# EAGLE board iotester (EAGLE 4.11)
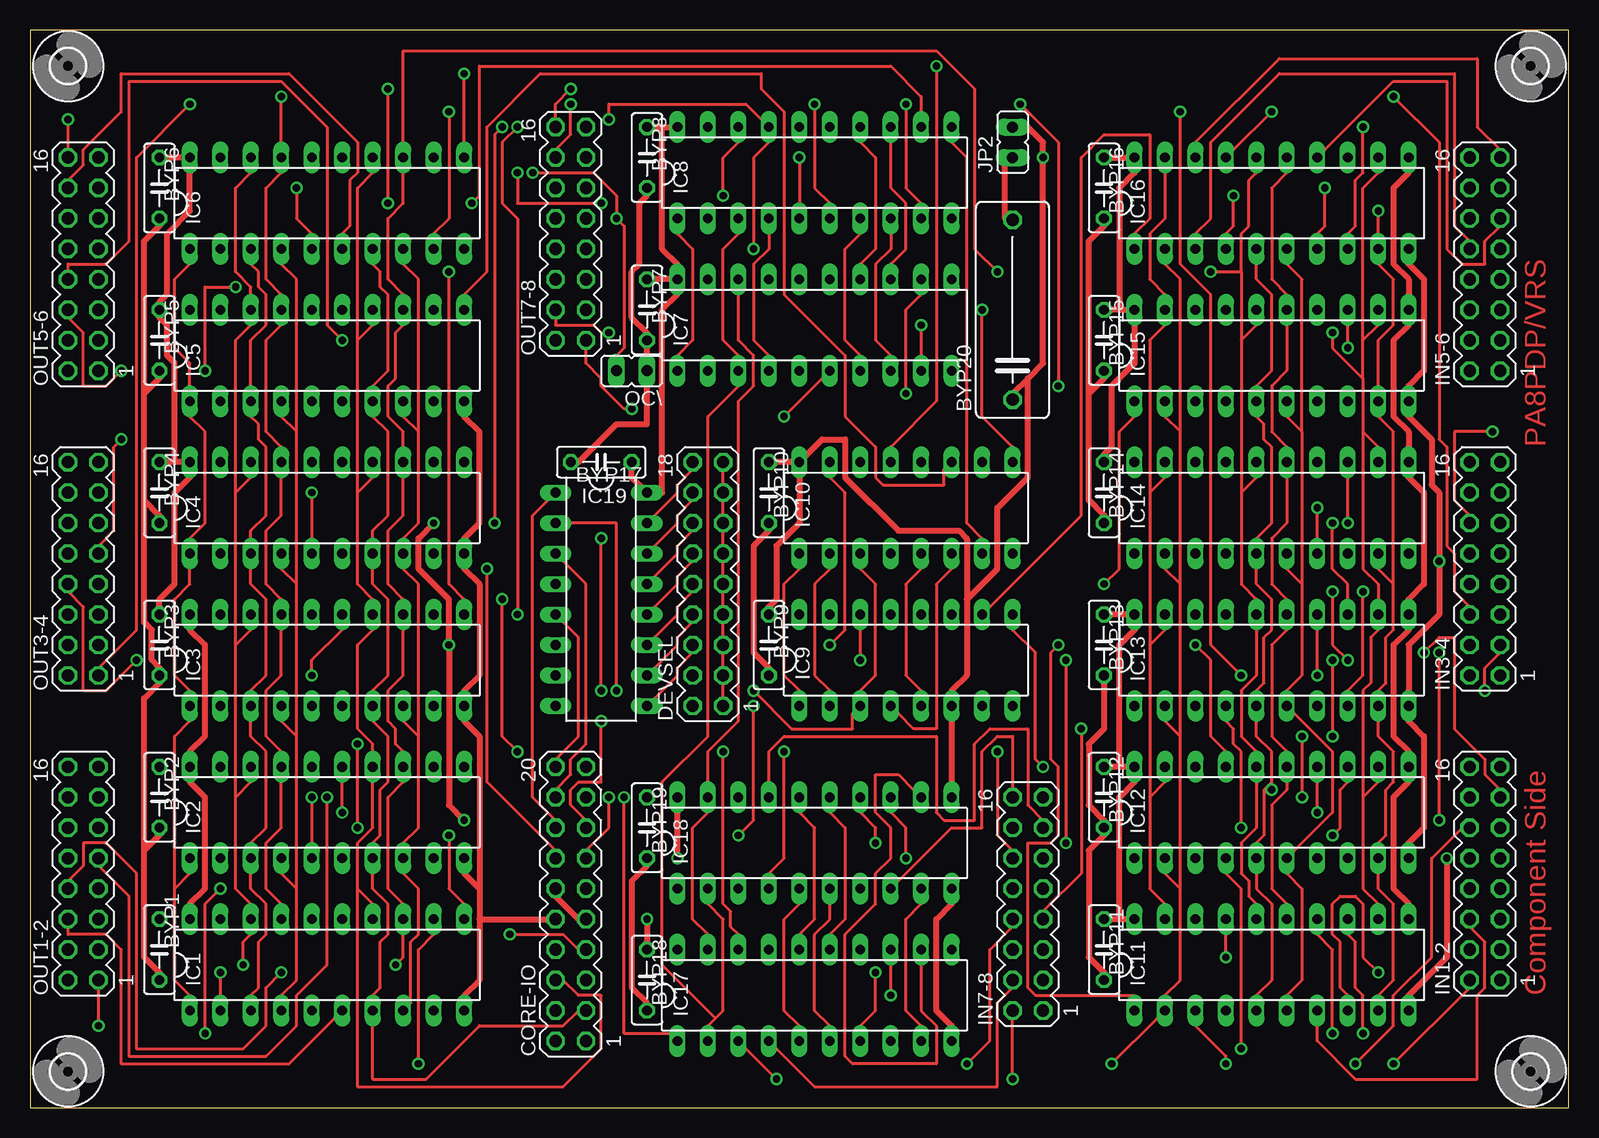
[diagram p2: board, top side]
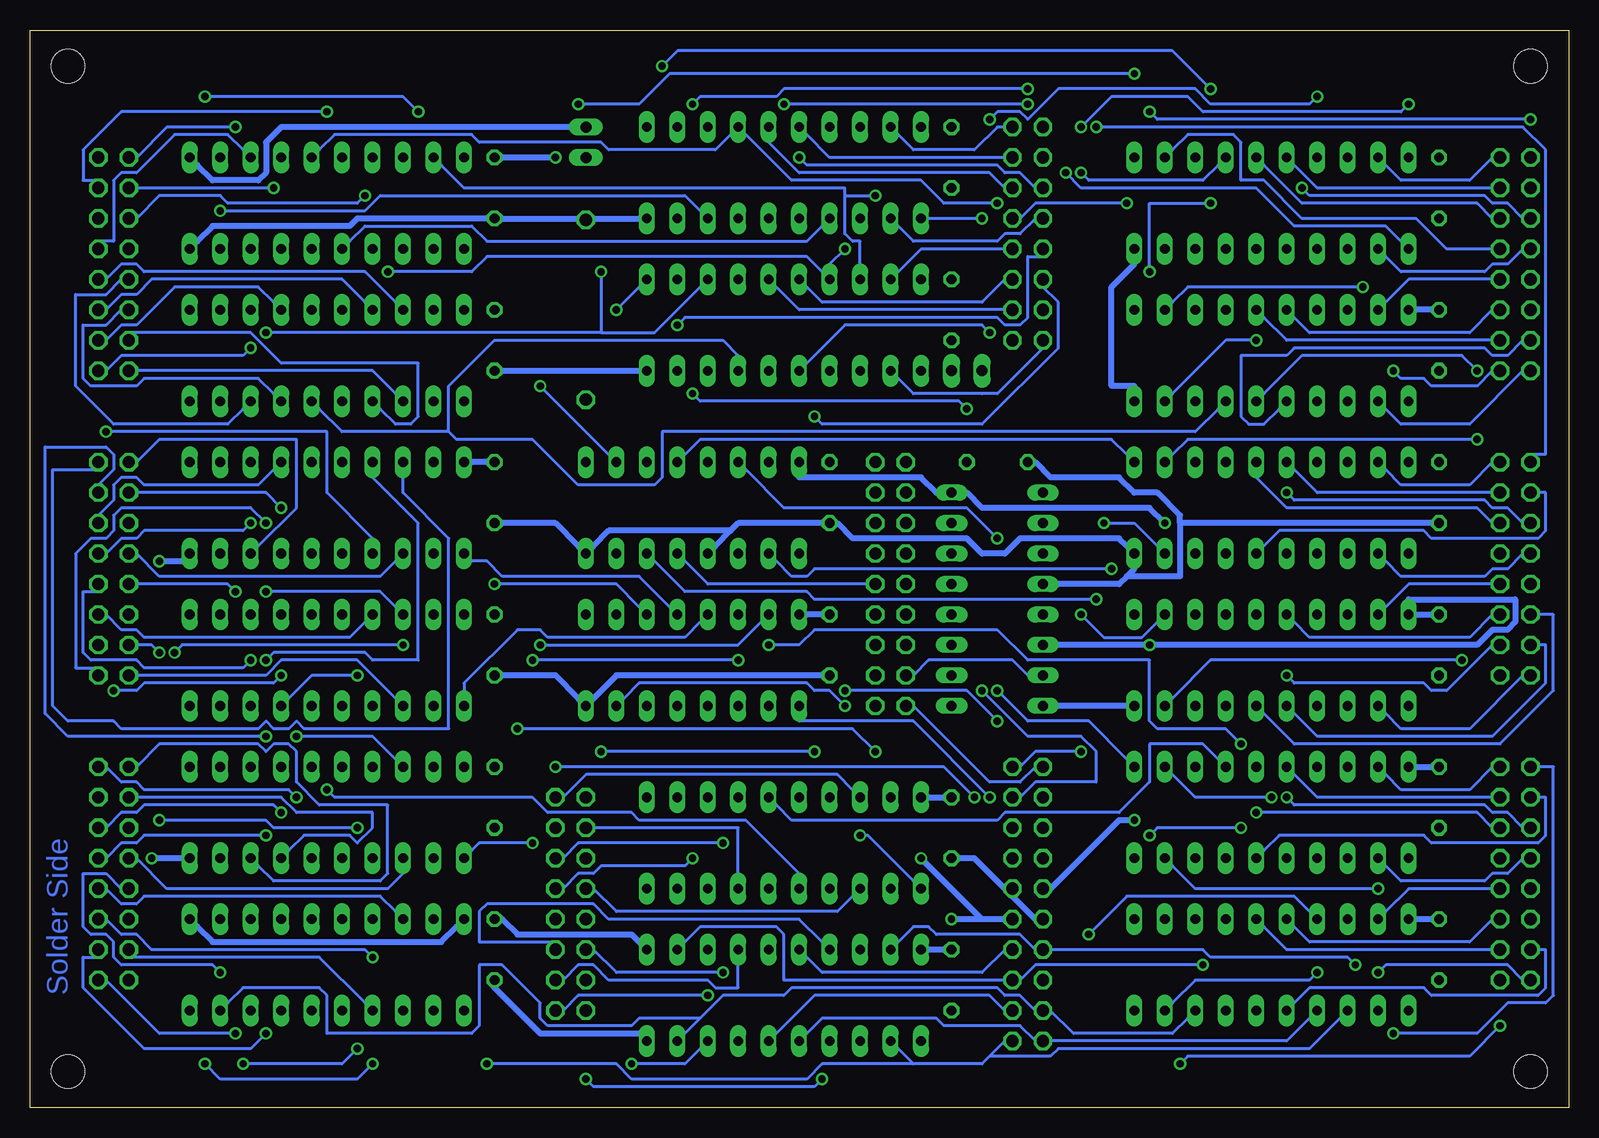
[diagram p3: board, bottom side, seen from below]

Size 128.25 x 89.84 mm. Coordinates in mm from the lower left corner, seen from the top.
Outline: 0,0 128.25,0 128.25,89.84 0,89.84 0,0
Copper layers (1*16): Top 0.035mm / dielectric 1.5mm / Bottom 0.035mm
Design rules "olimex10mil": minimum track width 10mil, minimum drill 24mil, track to track 10mil, track to pad 10mil, pad to pad 10mil, via to via 10mil, smd to smd 10mil, copper to edge 40mil, drill to drill 10mil, minimum pad ring 10mil, minimum via ring 8mil, stop-mask expansion 0mil, vias tented up to drill 0mil, thermal gap 10mil
Net classes: 1 Power: width 0.508 mm, drill 0.254 mm, clearance 0.254 mm

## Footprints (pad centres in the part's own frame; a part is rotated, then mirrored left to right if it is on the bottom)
C050-025X075 = drill 0.813 octagon: 1 -2.54,0; 2 2.54,0
C150-064X183 = drill 1.016 octagon: 1 -7.493,0; 2 7.493,0
MA10-2 = drill 1.016 octagon: 1 -11.43,-1.27; 2 -11.43,1.27; 3 -8.89,-1.27; 4 -8.89,1.27; 5 -6.35,-1.27; 6 -6.35,1.27; 7 -3.81,-1.27; 8 -3.81,1.27; 9 -1.27,-1.27; 10 -1.27,1.27; 11 1.27,-1.27; 12 1.27,1.27; 13 3.81,-1.27; 14 3.81,1.27; 15 6.35,-1.27; 16 6.35,1.27; 17 8.89,-1.27; 18 8.89,1.27; 19 11.43,-1.27; 20 11.43,1.27
MA09-2 = drill 1.016 octagon: 1 -10.16,-1.27; 2 -10.16,1.27; 3 -7.62,-1.27; 4 -7.62,1.27; 5 -5.08,-1.27; 6 -5.08,1.27; 7 -2.54,-1.27; 8 -2.54,1.27; 9 0,-1.27; 10 0,1.27; 11 2.54,-1.27; 12 2.54,1.27; 13 5.08,-1.27; 14 5.08,1.27; 15 7.62,-1.27; 16 7.62,1.27; 17 10.16,-1.27; 18 10.16,1.27
DIL20 = drill 0.813 long: 1 -11.43,-3.81; 2 -8.89,-3.81; 3 -6.35,-3.81; 4 -3.81,-3.81; 5 -1.27,-3.81; 6 1.27,-3.81; 7 3.81,-3.81; 8 6.35,-3.81; 9 8.89,-3.81; 10 11.43,-3.81; 11 11.43,3.81; 12 8.89,3.81; 13 6.35,3.81; 14 3.81,3.81; 15 1.27,3.81; 16 -1.27,3.81; 17 -3.81,3.81; 18 -6.35,3.81; 19 -8.89,3.81; 20 -11.43,3.81
DIL16 = drill 0.813 long: 1 -8.89,-3.81; 2 -6.35,-3.81; 3 -3.81,-3.81; 4 -1.27,-3.81; 5 1.27,-3.81; 6 3.81,-3.81; 7 6.35,-3.81; 8 8.89,-3.81; 9 8.89,3.81; 10 6.35,3.81; 11 3.81,3.81; 12 1.27,3.81; 13 -1.27,3.81; 14 -3.81,3.81; 15 -6.35,3.81; 16 -8.89,3.81
MA08-2 = drill 1.016 octagon: 1 -8.89,-1.27; 2 -8.89,1.27; 3 -6.35,-1.27; 4 -6.35,1.27; 5 -3.81,-1.27; 6 -3.81,1.27; 7 -1.27,-1.27; 8 -1.27,1.27; 9 1.27,-1.27; 10 1.27,1.27; 11 3.81,-1.27; 12 3.81,1.27; 13 6.35,-1.27; 14 6.35,1.27; 15 8.89,-1.27; 16 8.89,1.27
JP1 = drill 0.914 long: 1 0,-1.27; 2 0,1.27
2,8 = hole 2.8: 0,0

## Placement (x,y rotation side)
BYP1  0.1uf  [C050-025X075]  10.79,13.17 270 top
BYP2  0.1uf  [C050-025X075]  10.79,25.87 270 top
BYP3  0.1uf  [C050-025X075]  10.79,38.57 270 top
BYP4  0.1uf  [C050-025X075]  10.79,51.27 270 top
BYP5  0.1uf  [C050-025X075]  10.79,63.97 270 top
BYP6  0.1uf  [C050-025X075]  10.79,76.67 270 top
BYP7  0.1uf  [C050-025X075]  51.43,66.51 270 top
BYP8  0.1uf  [C050-025X075]  51.43,79.21 270 top
BYP9  0.1uf  [C050-025X075]  61.59,38.57 270 top
BYP10  0.1uf  [C050-025X075]  61.59,51.27 270 top
BYP11  0.1uf  [C050-025X075]  89.53,13.17 270 top
BYP12  0.1uf  [C050-025X075]  89.53,25.87 270 top
BYP13  0.1uf  [C050-025X075]  89.53,38.57 270 top
BYP14  0.1uf  [C050-025X075]  89.53,51.27 270 top
BYP15  0.1uf  [C050-025X075]  89.53,63.97 270 top
BYP16  0.1uf  [C050-025X075]  89.53,76.67 270 top
BYP17  0.1uf  [C050-025X075]  47.62,53.81 180 top
BYP18  0.1uf  [C050-025X075]  51.43,10.63 270 top
BYP19  0.1uf  [C050-025X075]  51.43,23.33 270 top
BYP20  100uf 25V  [C150-064X183]  81.91,66.51 90 top
CORE-IO  [MA10-2]  45.08,16.98 90 top
DEVSEL  [MA09-2]  56.51,43.65 90 top
IC1  374N  [DIL20]  24.76,11.9 0 top
IC2  374N  [DIL20]  24.76,24.6 0 top
IC3  374N  [DIL20]  24.76,37.3 0 top
IC4  374N  [DIL20]  24.76,50 0 top
IC5  374N  [DIL20]  24.76,62.7 0 top
IC6  374N  [DIL20]  24.76,75.4 0 top
IC7  374N  [DIL20]  65.4,65.24 0 top
IC8  374N  [DIL20]  65.4,77.94 0 top
IC9  138N  [DIL16]  73.02,37.3 0 top
IC10  138N  [DIL16]  73.02,50 0 top
IC11  373N  [DIL20]  103.5,11.9 0 top
IC12  373N  [DIL20]  103.5,24.6 0 top
IC13  373N  [DIL20]  103.5,37.3 0 top
IC14  373N  [DIL20]  103.5,50 0 top
IC15  373N  [DIL20]  103.5,62.7 0 top
IC16  373N  [DIL20]  103.5,75.4 0 top
IC17  373N  [DIL20]  65.4,9.36 0 top
IC18  373N  [DIL20]  65.4,22.06 0 top
IC19  138N  [DIL16]  47.62,42.38 270 top
IN1-2  [MA08-2]  121.28,19.52 90 top
IN3-4  [MA08-2]  121.28,44.92 90 top
IN5-6  [MA08-2]  121.28,70.32 90 top
IN7-8  [MA08-2]  83.18,16.98 90 top
JP2  POWER  [JP1]  81.91,80.48 0 top
OC\  POWER  [JP1]  50.16,61.43 90 top
OUT1-2  [MA08-2]  4.44,19.52 90 top
OUT3-4  [MA08-2]  4.44,44.92 90 top
OUT5-6  [MA08-2]  4.44,70.32 90 top
OUT7-8  [MA08-2]  45.08,72.86 90 top
U$1  [2,8]  125.09,3.01 0 top
U$2  [2,8]  125.09,86.83 0 top
U$3  [2,8]  3.17,86.83 0 top
U$4  [2,8]  3.17,3.01 0 top

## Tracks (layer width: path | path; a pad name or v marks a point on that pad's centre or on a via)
GND  (via drill 0.61)
  Top 0.508: 9.52,21.42 9.52,12.54 10.79,11.27 BYP1.2 | 9.52,21.42 10.79,22.7 BYP2.2 | 9.52,21.42 9.52,34.12 10.79,35.39 BYP3.2 10.79,36.66 10.16,37.3 10.16,39.84 9.52,40.48 9.52,50.63 | 9.52,50.63 10.79,49.37 BYP4.2 | 9.52,50.63 9.52,59.52 | 9.52,59.52 10.79,60.8 BYP5.2 | 9.52,59.52 9.52,72.22 10.79,73.5 BYP6.2 | BYP18.2 51.43,8.73 50.16,10 50.16,18.88 51.43,20.15 BYP19.2 | 37.46,18.25 37.46,15.71 | 37.46,15.71 37.46,10.63 36.19,9.36 IC1.10 | 37.46,18.25 36.19,19.52 IC2.10 | 37.46,18.25 37.46,30.95 36.19,32.22 IC3.10 36.19,34.76 37.46,36.03 37.46,43.65 36.19,44.92 IC4.10 36.19,47.46 37.46,48.73 37.46,56.35 36.19,57.62 IC5.10 | 37.46,15.71 43.18,15.71 CORE-IO.10 | 51.43,60.16 51.43,56.98 48.89,56.98 45.72,53.81 BYP17.2 | 51.43,60.16 OC\.1 | OC\.1 51.43,63.34 BYP7.2 51.43,64.61 50.16,65.88 50.16,69.69 50.8,70.32 50.8,75.4 51.43,76.03 BYP8.2 | IC16.10 114.93,70.32 116.2,69.05 116.2,61.43 114.93,60.16 IC15.10 114.93,57.62 116.83,55.71 116.83,51.91 117.47,51.27 v117.47,45.55 117.47,41.11 114.93,38.57 114.93,34.76 IC13.10 114.93,32.22 116.2,30.95 116.2,23.33 114.93,22.06 IC12.10 | v118.1,20.79 118.1,12.54 114.93,9.36 IC11.10 | IC17.10 76.83,6.82 75.56,8.09 75.56,15.71 76.83,16.98 IC18.10 | BYP11.2 89.53,11.27 88.26,12.54 88.26,21.42 89.53,22.7 BYP12.2 89.53,23.96 88.26,25.23 88.26,30.31 89.53,31.58 89.53,35.39 BYP13.2 | JP2.1 81.27,78.58 81.27,74.13 BYP20.2 | BYP9.2 61.59,36.66 60.32,37.94 60.32,46.82 61.59,48.09 BYP10.2 | 88.26,59.52 89.53,60.8 BYP15.2 | 88.26,59.52 88.26,50.63 89.53,49.37 BYP14.2 | 88.26,59.52 88.26,72.22 89.53,73.5 BYP16.2 | 51.43,60.16 OC\.1
  Bottom 0.508: CORE-IO.10 44.45,15.71 46.35,17.61 CORE-IO.11 46.98,18.25 49.53,20.79 50.8,20.79 BYP19.2 | IC3.10 36.83,33.49 42.54,33.49 IC19.8 | 36.83,44.28 37.46,43.65 42.54,43.65 IC19.4 | 36.83,44.28 36.19,44.92 IC4.10 36.83,46.82 37.46,47.46 45.72,47.46 46.98,46.19 48.89,46.19 50.16,47.46 59.69,47.46 60.96,48.73 BYP10.2 62.23,48.73 69.21,48.73 69.84,48.09 | IC6.10 36.19,70.32 38.1,68.41 38.1,60.16 36.19,60.16 IC5.10 | 32.38,48.73 32.38,44.28 36.83,44.28 | 32.38,48.73 32.38,49.37 34.29,51.27 36.19,51.27 37.46,52.54 43.18,52.54 44.45,53.81 BYP17.2 | 32.38,48.73 11.43,48.73 BYP4.2 | v118.1,20.79 115.56,20.79 IC12.10 | v117.47,45.55 115.56,45.55 IC14.10 | BYP11.2 89.53,10 85.72,6.18 77.46,6.18 IC17.10 | IC8.10 77.46,74.13 81.27,74.13 BYP20.2 82.55,74.13 88.89,74.13 BYP16.2 90.16,74.13 100.96,74.13 101.59,73.5 113.02,73.5 114.3,72.22 IC16.10 | IC7.10 77.46,61.43 88.89,61.43 BYP15.2 | BYP14.2 88.89,48.73 84.45,48.73 82.55,46.82 IC10.8 81.27,46.82 80,48.09 69.84,48.09 | BYP13.2 88.89,36.03 84.45,36.03 82.55,34.12 IC9.8 81.27,34.12 79.37,36.03 62.23,36.03 BYP9.2 | 69.84,48.09 71.11,46.82 IC10.4
IN00  (via drill 0.61)
  Top 0.254: v85.72,38.57 85.08,37.94 85.08,29.04 85.72,28.41 85.72,22.7 85.08,22.06 83.18,22.06 83.18,10 83.81,9.36 92.07,9.36 IC11.1
  Bottom 0.254: v85.72,38.57 69.21,38.57 67.3,40.48 IC9.15
IN01  (via drill 0.61)
  Top 0.254: v86.35,37.3 v86.35,22.06 | v69.21,37.3 69.21,39.84 IC9.14
  Bottom 0.254: v86.35,22.06 90.8,22.06 91.44,21.42 IC12.1 | v69.21,37.3 v86.35,37.3
IN02
  Bottom 0.254: IC9.13 72.38,40.48 73.66,39.2 85.08,39.2 85.72,39.84 87.62,39.84 92.07,35.39 92.07,34.76 IC13.1
IN03
  Bottom 0.254: IC9.12 74.92,41.74 77.46,44.28 88.89,44.28 90.16,45.55 91.44,45.55 IC14.1
IN04  (via drill 0.61)
  Top 0.254: v89.53,43.65 90.8,44.92 90.8,56.35 92.07,57.62 IC15.1
  Bottom 0.254: v89.53,43.65 79.37,43.65 77.46,41.74 IC9.11
IN05
  Top 0.254: IC9.10 80,41.74 87.62,49.37 87.62,79.21 89.53,81.11 93.34,81.11 93.34,74.13 92.07,72.86 IC16.1
IN06  (via drill 0.61)
  Top 0.254: v49.53,25.87 49.53,6.18 53.34,6.18 IC17.1 | v84.45,28.41 83.81,29.04 83.81,37.94 81.91,39.84 IC9.9
  Bottom 0.254: v49.53,25.87 52.07,28.41 v84.45,28.41
IN07  (via drill 0.61)
  Top 0.254: v59.05,22.7 60.32,23.96 v60.32,33.49
  Bottom 0.254: v59.05,22.7 58.41,22.7 54.61,18.88 IC18.1 | v60.32,33.49 61.59,34.76 62.86,34.76 63.5,35.39 77.46,35.39 78.73,34.12 IC9.7
N$1
  Bottom 0.254: IC12.3 97.15,19.52 98.42,18.25 116.83,18.25 119.38,20.79 IN1-2.10
N$2  (via drill 0.61)
  Top 0.254: v100.96,4.92 100.96,18.25 99.69,19.52 IC12.4 | v110.48,3.64 113.66,6.82 113.66,9.36 116.83,12.54 116.83,20.79 119.38,23.33 IN1-2.12
  Bottom 0.254: v100.96,4.92 102.23,3.64 v110.48,3.64
N$3
  Top 0.254: IC19.15 52.07,49.37 53.97,51.27 53.97,51.91 55.24,53.17 DEVSEL.18
N$4
  Top 0.254: IC19.14 52.07,46.82 53.97,48.73 53.97,49.37 55.24,50.63 DEVSEL.16
N$5
  Top 0.254: IC19.13 52.07,44.28 53.97,46.19 53.97,46.82 55.24,48.09 DEVSEL.14
N$6
  Top 0.254: IC19.12 52.07,41.74 53.97,43.65 53.97,44.28 55.24,45.55 DEVSEL.12
N$7
  Bottom 0.254: IC12.7 106.67,21.42 105.41,22.7 101.59,22.7 100.96,22.06 99.69,23.33 99.69,24.6 106.04,24.6 107.31,25.87 119.38,25.87 IN1-2.14
N$8
  Bottom 0.254: IC12.8 109.21,20.15 107.94,18.88 99.05,18.88 98.42,19.52 98.42,25.23 104.13,25.23 106.04,27.14 106.04,29.68 106.67,30.31 107.94,30.31 108.58,29.68 109.21,30.31 117.47,30.31 119.38,28.41 IN1-2.16
N$9  (via drill 0.61)
  Top 0.254: v112.39,11.27 111.12,12.54 111.12,16.98 110.48,17.61 109.21,17.61 108.58,16.98 108.58,14.44 109.21,13.81 109.21,10 109.85,9.36 IC11.8
  Bottom 0.254: v112.39,11.27 113.02,11.9 120.64,11.9 121.28,12.54 121.28,13.81 121.91,14.44 123.19,14.44 123.82,15.08 123.82,19.52 121.91,19.52 120.64,18.25 IN1-2.8
N$10
  Top 0.254: IC11.7 107.31,6.82 107.31,5.55 110.48,2.38 120.64,2.38 120.64,9.36 121.28,10 121.28,13.81 120.01,15.08 IN1-2.6
N$11
  Bottom 0.254: IC11.4 100.32,8.73 104.13,12.54 120.01,12.54 IN1-2.4
N$12  (via drill 0.61)
  Top 0.254: v99.69,3.64 99.69,4.28 97.15,6.82 IC11.3 | v113.66,3.64 120.01,10 IN1-2.2
  Bottom 0.254: v99.69,3.64 100.96,2.38 112.39,2.38 v113.66,3.64
N$13  (via drill 0.61)
  Top 0.254: v111.12,6.18 111.12,9.36 110.48,10 110.48,13.81 109.85,14.44 IC11.13
  Bottom 0.254: v111.12,6.18 117.47,6.18 121.91,10.63 IN1-2.1
N$14  (via drill 0.61)
  Top 0.254: v108.58,6.18 108.58,13.17 107.31,14.44 IC11.14
  Bottom 0.254: v108.58,6.18 109.85,4.92 118.74,4.92 123.82,10 123.82,12.54 122.55,12.54 IN1-2.3
N$15  (via drill 0.61)
  Top 0.254: v99.69,12.54 99.69,14.44 IC11.17
  Bottom 0.254: v99.69,12.54 100.32,13.17 118.1,13.17 119.38,14.44 120.64,14.44 121.91,15.71 IN1-2.5
N$16
  Bottom 0.254: IC11.18 97.78,16.34 99.05,17.61 118.74,17.61 119.38,16.98 120.64,16.98 121.91,18.25 IN1-2.7
N$17  (via drill 0.61)
  Top 0.254: v108.58,22.7 109.21,23.33 109.21,26.5 109.85,27.14 IC12.13
  Bottom 0.254: v108.58,22.7 118.74,22.7 119.38,22.06 120.64,22.06 121.91,20.79 IN1-2.9
N$18  (via drill 0.61)
  Top 0.254: v107.31,24.6 107.31,27.14 IC12.14
  Bottom 0.254: v107.31,24.6 107.94,25.23 118.74,25.23 119.38,24.6 120.64,24.6 121.91,23.33 IN1-2.11
N$19  (via drill 0.61)
  Top 0.254: v97.15,38.57 98.42,37.3 98.42,30.95 99.69,29.68 IC12.17 | v116.2,37.94 117.47,39.2 118.74,39.2 118.74,31.58 121.28,29.04 121.28,27.77 122.55,26.5 IN1-2.13
  Bottom 0.254: v97.15,38.57 115.56,38.57 v116.2,37.94
N$20  (via drill 0.61)
  Top 0.254: v106.04,30.95 v106.04,25.87
  Bottom 0.254: v106.04,30.95 99.69,30.95 97.78,29.04 IC12.18 | v106.04,25.87 106.67,26.5 118.74,26.5 119.38,27.14 120.64,27.14 121.91,28.41 IN1-2.15
N$21
  Top 0.254: IC19.11 52.07,39.2 53.97,41.11 53.97,41.74 55.24,43.02 DEVSEL.10
N$22
  Top 0.254: IC19.10 52.07,36.66 53.97,38.57 53.97,39.2 55.24,40.48 DEVSEL.8
N$23
  Top 0.254: IC19.9 52.07,34.12 53.97,36.03 53.97,36.66 55.24,37.94 DEVSEL.6
N$24
  Bottom 0.254: IC19.7 45.08,36.03 46.35,37.3 53.34,37.3 54.61,36.03 DEVSEL.4
N$25
  Top 0.254: IC9.5 74.29,34.76 73.02,36.03 73.02,43.65 74.29,44.92 IC10.5 | DEVSEL.1 57.78,34.12 57.78,35.39 DEVSEL.3 57.78,36.66 57.78,37.94 DEVSEL.5 57.78,39.2 57.78,40.48 DEVSEL.7 57.78,41.74 57.78,43.02 DEVSEL.9 57.78,44.28 57.78,45.55 DEVSEL.11 57.78,46.82 57.78,48.09 DEVSEL.13 57.78,49.37 57.78,50.63 DEVSEL.15 57.78,51.91 57.78,53.17 DEVSEL.17
  Bottom 0.254: IC10.5 73.66,45.55 71.75,43.65 58.41,43.65 DEVSEL.9
N$26
  Bottom 0.254: IC5.2 15.24,58.25 13.97,56.98 8.25,56.98 3.8,61.43 OUT5-6.2
N$27
  Top 0.254: IC18.8 72.38,18.88 76.83,23.33 79.37,23.33 79.37,29.68 80.64,30.95 81.91,30.95 81.91,26.5 IN7-8.16
N$28
  Bottom 0.254: IC18.3 59.69,17.61 60.96,16.34 79.37,16.34 81.27,18.25 IN7-8.10
N$29
  Bottom 0.254: IC14.3 97.78,45.55 99.05,44.28 117.47,44.28 119.38,46.19 IN3-4.10
N$30  (via drill 0.61)
  Top 0.254: v121.91,56.35 118.74,56.35 118.74,50.63 120.01,49.37 IN3-4.12
  Bottom 0.254: v121.91,56.35 103.5,56.35 103.5,51.27 99.69,47.46 IC14.4
N$31  (via drill 0.61)
  Top 0.254: v107.31,50 107.31,47.46 IC14.7
  Bottom 0.254: v107.31,50 108.58,51.27 119.38,51.27 IN3-4.14
N$32
  Bottom 0.254: IC14.8 109.21,46.82 106.04,50 106.04,55.71 117.47,55.71 119.38,53.81 IN3-4.16
N$33  (via drill 0.61)
  Top 0.254: v40.64,41.11 40.64,74.13 39.37,75.4 39.37,80.48 v40.64,81.75 | v13.33,83.66 8.89,79.21 8.89,39.84 5.71,36.66 OUT3-4.1
  Bottom 0.254: v40.64,41.11 38.73,39.2 35.55,39.2 34.29,40.48 IC3.12 | v40.64,81.75 38.1,84.29 31.74,84.29 30.47,83.02 13.97,83.02 v13.33,83.66
N$34  (via drill 0.61)
  Top 0.254: v23.49,36.03 23.49,37.3 26.03,39.84 IC3.15
  Bottom 0.254: v23.49,36.03 22.86,35.39 12.06,35.39 11.43,34.76 10.16,34.76 6.34,38.57 OUT3-4.3
N$35
  Bottom 0.254: IC3.16 22.86,40.48 21.58,39.2 8.25,39.2 6.34,41.11 OUT3-4.5
N$36
  Bottom 0.254: IC3.19 15.24,41.74 13.33,43.65 6.34,43.65 OUT3-4.7
N$37
  Bottom 0.254: IC13.3 97.78,34.12 100.96,37.3 107.31,37.3 108.58,36.03 119.38,36.03 IN3-4.2
N$38  (via drill 0.61)
  Top 0.254: v100.96,23.33 100.96,29.68 100.32,30.31 100.32,31.58 99.69,32.22 IC13.4 | v117.47,23.96 v117.47,37.94
  Bottom 0.254: v100.96,23.33 107.94,23.33 108.58,23.96 v117.47,23.96 | v117.47,37.94 118.1,38.57 119.38,38.57 IN3-4.4
N$39  (via drill 0.61)
  Top 0.254: v100.96,36.03 98.42,38.57 98.42,67.78 95.88,70.32 v95.88,83.02 | v113.66,84.29 117.47,80.48 117.47,55.71 118.1,55.08 118.1,46.82 118.74,46.19 118.74,43.02 120.01,41.74 IN3-4.6
  Bottom 0.254: v100.96,36.03 104.77,36.03 106.67,34.12 IC13.7 | v95.88,83.02 97.15,84.29 v113.66,84.29
N$40  (via drill 0.61)
  Top 0.254: v111.12,43.02 111.12,36.03 109.85,34.76 IC13.8
  Bottom 0.254: v111.12,43.02 111.75,43.65 119.38,43.65 IN3-4.8
N$41  (via drill 0.61)
  Top 0.254: v109.85,48.73 109.85,52.54 IC14.13
  Bottom 0.254: v109.85,48.73 110.48,48.09 118.74,48.09 119.38,47.46 120.64,47.46 121.91,46.19 IN3-4.9
N$42
  Bottom 0.254: IC14.14 107.94,53.17 109.21,51.91 118.74,51.91 119.38,52.54 120.64,52.54 121.28,51.91 121.28,50.63 122.55,49.37 IN3-4.11
N$43  (via drill 0.61)
  Top 0.254: v108.58,37.3 v108.58,30.95
  Bottom 0.254: v108.58,37.3 107.94,37.94 100.32,37.94 99.69,37.3 95.88,37.3 95.88,48.73 99.69,52.54 IC14.17 | v108.58,30.95 125.09,30.95 126.99,32.85 126.99,55.08 121.91,55.08 121.28,54.45 121.28,53.17 122.55,51.91 IN3-4.13
N$44
  Bottom 0.254: IC14.18 97.15,52.54 97.15,51.27 93.34,47.46 93.34,31.58 105.41,31.58 106.04,32.22 106.67,31.58 107.94,31.58 108.58,32.22 109.21,31.58 120.64,31.58 121.28,32.22 125.09,32.22 126.36,33.49 126.36,53.17 122.55,53.17 IN3-4.15
N$45  (via drill 0.61)
  Top 0.254: v108.58,48.73 108.58,44.92 109.85,43.65 109.85,42.38 IC13.13
  Bottom 0.254: v108.58,48.73 109.85,50 120.64,50 121.28,49.37 121.28,48.09 121.91,47.46 123.19,47.46 124.45,46.19 124.45,36.66 122.55,36.66 IN3-4.1
N$46  (via drill 0.61)
  Top 0.254: v107.31,36.03 107.31,39.84 IC13.14 | v121.28,34.76 121.28,36.66 122.55,37.94 IN3-4.3
  Bottom 0.254: v107.31,36.03 107.94,35.39 118.74,35.39 119.38,34.76 v121.28,34.76
N$47
  Bottom 0.254: IC13.17 100.32,40.48 101.59,39.2 118.74,39.2 119.38,39.84 120.64,39.84 121.91,41.11 IN3-4.5
N$48  (via drill 0.61)
  Top 0.254: v108.58,43.02 108.58,38.57 v109.85,37.3
  Bottom 0.254: v108.58,43.02 99.05,43.02 97.78,41.74 IC13.18 | v109.85,37.3 110.48,36.66 118.74,36.66 119.38,37.3 123.19,37.3 123.82,37.94 123.82,43.02 122.55,43.02 IN3-4.7
N$49
  Bottom 0.254: IC3.5 22.86,32.85 20.95,30.95 6.34,30.95 1.9,35.39 1.9,38.57 2.54,38.57 OUT3-4.4
N$50
  Bottom 0.254: IC3.6 25.39,32.85 22.86,30.31 5.71,30.31 1.27,34.76 1.27,41.11 2.54,41.11 OUT3-4.6
N$51
  Bottom 0.254: IC3.2 15.24,32.85 13.97,31.58 8.25,31.58 3.8,36.03 OUT3-4.2
N$52  (via drill 0.61)
  Top 0.254: v8.89,37.3 6.34,34.76 4.44,34.76 4.44,41.74 3.17,43.02 OUT3-4.8
  Bottom 0.254: v8.89,37.3 29.84,37.3 33.02,34.12 IC3.9
N$53  (via drill 0.61)
  Top 0.254: v32.38,3.64 32.38,13.17 33.65,14.44 IC1.12 | v5.71,6.82 5.71,10 OUT1-2.1
  Bottom 0.254: v32.38,3.64 31.74,4.28 8.25,4.28 v5.71,6.82
N$54
  Bottom 0.254: IC1.15 25.39,15.08 23.49,13.17 6.34,13.17 OUT1-2.3
N$55
  Bottom 0.254: IC1.16 22.86,15.08 21.58,13.81 8.25,13.81 6.34,15.71 OUT1-2.5
N$56
  Bottom 0.254: IC1.19 15.24,16.34 13.33,18.25 6.34,18.25 OUT1-2.7
N$57  (via drill 0.61)
  Top 0.254: v15.87,11.27 15.87,9.36 IC1.2
  Bottom 0.254: v15.87,11.27 15.24,11.9 5.08,11.9 3.8,10.63 OUT1-2.2
N$58
  Bottom 0.254: IC1.5 22.86,8.73 21.58,10 12.06,10 11.43,9.36 2.54,9.36 1.9,10 1.9,13.17 2.54,13.17 OUT1-2.4
N$59
  Top 0.254: IC1.6 25.39,7.46 21.58,3.64 7.62,3.64 7.62,13.17 6.34,14.44 3.17,14.44 3.17,15.08 OUT1-2.6
N$60  (via drill 0.61)
  Top 0.254: v20.95,11.27 19.68,10 19.68,6.82 17.77,4.92 8.89,4.92 8.89,19.52 6.34,22.06 4.44,22.06 4.44,20.15 3.17,18.88 OUT1-2.8
  Bottom 0.254: v20.95,11.27 21.58,10.63 31.11,10.63 33.02,8.73 IC1.9
N$61
  Bottom 0.254: IC2.19 15.24,27.77 13.97,26.5 8.25,26.5 6.34,28.41 OUT1-2.15
N$62
  Bottom 0.254: IC2.16 22.86,27.77 20.95,25.87 6.34,25.87 OUT1-2.13
N$63  (via drill 0.61)
  Top 0.254: v26.03,24.6 26.03,27.14 IC2.15
  Bottom 0.254: v26.03,24.6 7.62,24.6 6.34,23.33 OUT1-2.11
N$64  (via drill 0.61)
  Top 0.254: v24.76,25.87 24.76,11.9 22.22,9.36 22.22,6.82 19.68,4.28 8.25,4.28 8.25,17.61 5.71,20.15 OUT1-2.9
  Bottom 0.254: v24.76,25.87 31.11,25.87 33.02,27.77 IC2.12
N$65
  Bottom 0.254: IC2.2 15.24,20.15 13.97,18.88 6.98,18.88 6.34,19.52 5.08,19.52 3.8,20.79 OUT1-2.10
N$66  (via drill 0.61)
  Top 0.254: v23.49,25.87 23.49,22.06 IC2.5
  Bottom 0.254: v23.49,25.87 22.86,25.23 6.98,25.23 6.34,24.6 5.08,24.6 3.8,23.33 OUT1-2.12
N$67
  Bottom 0.254: IC2.6 25.39,21.42 24.12,22.7 12.06,22.7 11.43,22.06 2.54,22.06 1.9,22.7 1.9,25.87 2.54,25.87 OUT1-2.14
N$68  (via drill 0.61)
  Top 0.254: v15.87,18.25 14.6,16.98 v14.6,6.18
  Bottom 0.254: v15.87,18.25 31.11,18.25 33.02,20.15 IC2.9 | v14.6,6.18 7.62,6.18 5.08,8.73 1.9,8.73 1.27,9.36 1.27,28.41 2.54,28.41 OUT1-2.16
N$69
  Bottom 0.254: IC4.2 15.24,45.55 13.97,44.28 6.98,44.28 6.34,44.92 5.08,44.92 3.8,46.19 OUT3-4.10
N$70  (via drill 0.61)
  Top 0.254: v23.49,51.27 23.49,47.46 IC4.5
  Bottom 0.254: v23.49,51.27 22.86,50.63 6.98,50.63 6.34,50 5.08,50 3.8,48.73 OUT3-4.12
N$71
  Bottom 0.254: IC4.6 25.39,46.82 24.12,48.09 12.06,48.09 11.43,47.46 2.54,47.46 1.9,48.09 1.9,51.27 2.54,51.27 OUT3-4.14
N$72  (via drill 0.61)
  Top 0.254: v38.73,48.73 38.73,81.11 v39.37,81.75
  Bottom 0.254: v38.73,48.73 36.19,48.73 34.29,46.82 IC4.9 | v39.37,81.75 3.8,81.75 1.9,79.84 1.9,54.45 3.17,54.45 OUT3-4.16
N$73
  Bottom 0.254: IC4.19 15.24,53.17 13.97,51.91 8.25,51.91 6.34,53.81 OUT3-4.15
N$74
  Bottom 0.254: IC4.16 22.86,53.17 20.95,51.27 6.34,51.27 OUT3-4.13
N$75
  Bottom 0.254: IC4.15 26.03,52.54 23.49,50 7.62,50 6.34,48.73 OUT3-4.11
N$76  (via drill 0.61)
  Top 0.254: v7.62,55.71 6.98,55.08 6.98,48.09 5.71,46.82 OUT3-4.9
  Bottom 0.254: v7.62,55.71 31.74,55.71 33.02,54.45 IC4.12
N$77
  Top 0.254: IC16.3 97.15,72.86 98.42,74.13 98.42,80.48 104.13,86.19 118.74,86.19 118.74,73.5 120.01,72.22 IN5-6.10
N$78  (via drill 0.61)
  Top 0.254: v100.32,76.03 100.32,73.5 99.69,72.86 IC16.4
  Bottom 0.254: v100.32,76.03 100.96,75.4 111.75,75.4 112.39,76.03 117.47,76.03 119.38,74.13 IN5-6.12
N$79  (via drill 0.61)
  Top 0.254: v107.94,76.67 107.94,73.5 107.31,72.86 IC16.7
  Bottom 0.254: v107.94,76.67 119.38,76.67 IN5-6.14
N$80  (via drill 0.61)
  Top 0.254: v111.12,81.75 111.12,77.94 110.48,77.3 110.48,73.5 109.85,72.86 IC16.8
  Bottom 0.254: v111.12,81.75 116.83,81.75 119.38,79.21 IN5-6.16
N$81  (via drill 0.61)
  Top 0.254: v17.14,68.41 14.6,68.41 v14.6,61.43
  Bottom 0.254: v17.14,68.41 31.74,68.41 33.02,67.14 IC5.12 | v14.6,61.43 13.97,60.8 12.06,60.8 11.43,60.16 7.62,60.16 6.34,61.43 OUT5-6.1
N$82
  Bottom 0.254: IC5.15 25.39,65.88 23.49,63.97 6.34,63.97 OUT5-6.3
N$83
  Bottom 0.254: IC5.16 22.86,65.88 21.58,64.61 8.25,64.61 6.34,66.51 OUT5-6.5
N$84
  Bottom 0.254: IC5.19 15.24,67.14 13.33,69.05 6.34,69.05 OUT5-6.7
N$85  (via drill 0.61)
  Top 0.254: v73.02,59.52 73.02,66.51 74.29,67.78 IC7.12 | OUT7-8.1 46.35,63.34 46.35,62.06 47.62,60.8 47.62,60.16 49.53,58.25 v50.16,58.25
  Bottom 0.254: v73.02,59.52 72.38,58.89 50.8,58.89 v50.16,58.25
N$86
  Bottom 0.254: IC7.15 66.03,68.41 64.13,66.51 46.98,66.51 OUT7-8.3
N$87
  Bottom 0.254: IC7.16 63.5,68.41 62.23,67.14 48.89,67.14 46.98,69.05 OUT7-8.5
N$88
  Bottom 0.254: IC7.19 55.88,69.69 53.97,71.59 46.98,71.59 OUT7-8.7
N$89
  Bottom 0.254: IC5.5 24.12,58.25 25.39,56.98 26.66,56.98 27.3,57.62 27.3,62.7 23.49,62.7 22.86,63.34 6.98,63.34 6.34,62.7 5.08,62.7 3.8,63.97 OUT5-6.4
N$90  (via drill 0.61)
  Top 0.254: v7.62,61.43 6.34,60.16 4.44,60.16 4.44,64.61 3.17,65.88 OUT5-6.6
  Bottom 0.254: v7.62,61.43 8.89,62.7 22.22,62.7 25.39,59.52 IC5.6
N$91  (via drill 0.61)
  Top 0.254: v26.03,63.97 24.76,65.24 24.76,81.75 20.95,85.56 8.25,85.56 8.25,72.22 6.34,70.32 3.17,70.32 3.17,69.69 OUT5-6.8
  Bottom 0.254: v26.03,63.97 28.57,63.97 33.02,59.52 IC5.9
N$92
  Bottom 0.254: IC6.12 33.02,79.84 31.74,81.11 27.93,81.11 27.3,80.48 27.3,77.3 25.39,77.3 22.22,74.13 12.7,74.13 10.16,71.59 6.34,71.59 OUT5-6.9
N$93
  Bottom 0.254: IC6.15 25.39,78.58 22.22,75.4 7.62,75.4 6.34,74.13 OUT5-6.11
N$94  (via drill 0.61)
  Top 0.254: v62.86,29.68 62.86,20.79 61.59,19.52 IC18.4 | v80.64,29.68 80.64,22.7 81.91,21.42 IN7-8.12
  Bottom 0.254: v62.86,29.68 v80.64,29.68
N$95
  Bottom 0.254: IC6.16 22.86,78.58 20.95,76.67 6.34,76.67 OUT5-6.13
N$96
  Bottom 0.254: IC6.19 15.24,78.58 13.97,77.3 8.25,77.3 6.34,79.21 OUT5-6.15
N$97
  Bottom 0.254: IC6.2 15.24,70.95 13.97,69.69 6.98,69.69 6.34,70.32 5.08,70.32 3.8,71.59 OUT5-6.10
N$98  (via drill 0.61)
  Top 0.254: v22.22,76.67 22.22,74.13 23.49,72.86 IC6.5
  Bottom 0.254: v22.22,76.67 21.58,76.03 6.98,76.03 6.34,75.4 5.08,75.4 3.8,74.13 OUT5-6.12
N$99
  Top 0.254: IC6.6 26.03,72.86 26.66,73.5 26.66,77.3 27.3,77.94 27.3,80.48 21.58,86.19 7.62,86.19 7.62,83.02 4.44,79.84 4.44,78.58 3.17,77.3 OUT5-6.14
N$100  (via drill 0.61)
  Top 0.254: v34.92,83.02 34.92,74.13 33.65,72.86 IC6.9 | v3.17,82.39 3.17,79.84 OUT5-6.16
  Bottom 0.254: v34.92,83.02 34.29,82.39 v3.17,82.39
N$101
  Bottom 0.254: IC15.3 97.78,59.52 99.69,61.43 119.38,61.43 IN5-6.2
N$102
  Bottom 0.254: IC15.4 99.05,58.25 97.78,56.98 96.52,56.98 95.88,57.62 95.88,62.06 107.31,62.06 109.85,64.61 120.01,64.61 IN5-6.4
N$103
  Bottom 0.254: IC15.7 107.94,59.52 109.21,60.8 118.74,60.8 119.38,60.16 123.19,60.16 123.82,60.8 123.82,65.24 121.91,65.24 120.64,66.51 IN5-6.6
N$104
  Bottom 0.254: IC15.8 110.48,58.25 111.75,56.98 121.28,56.98 124.45,60.16 124.45,67.78 121.91,67.78 120.64,69.05 IN5-6.8
N$105
  Bottom 0.254: IC16.13 110.48,79.84 111.75,81.11 116.2,81.11 119.38,77.94 120.64,77.94 121.28,77.3 121.28,72.22 122.55,72.22 IN5-6.9
N$106
  Top 0.254: IC16.14 107.94,79.84 113.66,85.56 118.1,85.56 118.1,71.59 119.38,70.32 121.28,70.32 121.28,72.22 122.55,73.5 IN5-6.11
N$107  (via drill 0.61)
  Top 0.254: v103.5,83.02 100.32,79.84 IC16.17
  Bottom 0.254: v103.5,83.02 120.64,83.02 123.82,79.84 123.82,77.3 122.55,77.3 IN5-6.13
N$108
  Top 0.254: IC16.18 97.15,80.48 104.13,87.47 120.64,87.47 120.64,81.75 122.55,79.84 IN5-6.15
N$109  (via drill 0.61)
  Top 0.254: v109.85,63.34 109.85,65.24 IC15.13
  Bottom 0.254: v109.85,63.34 110.48,62.7 120.64,62.7 121.91,61.43 IN5-6.1
N$110
  Bottom 0.254: IC15.14 107.94,67.14 109.21,68.41 116.2,68.41 119.38,65.24 120.64,65.24 121.91,63.97 IN5-6.3
N$111
  Bottom 0.254: IC15.17 100.32,67.14 102.23,69.05 118.1,69.05 119.38,67.78 120.64,67.78 121.91,66.51 IN5-6.5
N$112
  Bottom 0.254: IC15.18 97.78,67.14 100.32,69.69 118.74,69.69 119.38,70.32 120.64,70.32 121.91,69.05 IN5-6.7
N$113
  Bottom 0.254: IC8.19 55.88,81.11 54.61,79.84 49.53,79.84 47.62,81.75 46.98,81.75 OUT7-8.15
N$114
  Bottom 0.254: IC8.16 63.5,81.11 61.59,79.21 46.98,79.21 OUT7-8.13
N$115
  Bottom 0.254: IC8.15 66.67,80.48 64.13,77.94 48.26,77.94 46.98,76.67 OUT7-8.11
N$116  (via drill 0.61)
  Top 0.254: v36.83,75.4 37.46,76.03 37.46,86.83 71.75,86.83 74.29,84.29 74.29,83.02 IC8.12
  Bottom 0.254: v36.83,75.4 44.45,75.4 45.72,74.13 OUT7-8.9
N$117
  Bottom 0.254: IC8.2 55.88,73.5 54.61,72.22 47.62,72.22 46.98,72.86 45.72,72.86 44.45,74.13 OUT7-8.10
N$118  (via drill 0.61)
  Top 0.254: v64.13,79.21 64.13,75.4 IC8.5
  Bottom 0.254: v64.13,79.21 63.5,78.58 47.62,78.58 46.98,77.94 45.72,77.94 44.45,76.67 OUT7-8.12
N$119  (via drill 0.61)
  Top 0.254: v65.4,83.66 65.4,76.67 66.67,75.4 IC8.6 | v45.08,83.66 45.08,81.11 43.81,79.84 OUT7-8.14
  Bottom 0.254: v45.08,83.66 v65.4,83.66
N$120  (via drill 0.61)
  Top 0.254: v73.02,83.66 73.02,76.67 74.29,75.4 IC8.9 | v45.08,84.92 43.81,83.66 43.81,82.39 OUT7-8.16
  Bottom 0.254: v73.02,83.66 72.38,84.29 66.03,84.29 65.4,84.92 v45.08,84.92
N$121  (via drill 0.61)
  Top 0.254: v74.29,65.24 74.29,62.7 IC7.9
  Bottom 0.254: v74.29,65.24 73.66,65.88 47.62,65.88 46.98,65.24 45.72,65.24 45.08,65.88 45.08,70.95 43.81,70.95 OUT7-8.8
N$122  (via drill 0.61)
  Top 0.254: v62.86,57.62 66.03,60.8 IC7.6
  Bottom 0.254: v62.86,57.62 62.23,56.98 48.89,56.98 42.54,63.34 42.54,67.14 43.81,68.41 OUT7-8.6
N$123  (via drill 0.61)
  Top 0.254: v48.26,64.61 47.62,64.61 46.98,65.24 43.81,65.24 43.81,65.88 OUT7-8.4
  Bottom 0.254: v48.26,64.61 48.89,65.24 60.32,65.24 63.5,62.06 IC7.5
N$124
  Bottom 0.254: IC18.7 69.21,19.52 69.21,23.33 81.27,23.33 IN7-8.14
N$125  (via drill 0.61)
  Top 0.254: v73.02,20.79 73.02,23.33 71.75,24.6 IC18.13
  Bottom 0.254: v73.02,20.79 73.66,20.15 80.64,20.15 81.27,19.52 82.55,19.52 83.81,18.25 IN7-8.9
N$126  (via drill 0.61)
  Top 0.254: v70.48,22.06 70.48,23.33 69.21,24.6 IC18.14
  Bottom 0.254: v70.48,22.06 82.55,22.06 83.81,20.79 IN7-8.11
N$127
  Top 0.254: IC18.17 61.59,27.14 61.59,29.68 62.86,30.95 75.56,30.95 75.56,24.6 76.19,23.96 78.73,23.96 78.73,30.31 80,31.58 83.18,31.58 83.18,25.23 84.45,23.96 IN7-8.13
N$128
  Bottom 0.254: IC18.18 59.69,26.5 60.96,27.77 81.91,27.77 83.81,25.87 IN7-8.15
N$129  (via drill 0.61)
  Top 0.254: v62.23,2.38 59.69,4.92 IC17.3 | v81.91,2.38 81.91,7.46 IN7-8.2
  Bottom 0.254: v62.23,2.38 62.86,1.74 81.27,1.74 v81.91,2.38
N$130
  Top 0.254: IC17.4 62.23,4.92 65.4,1.74 80.64,1.74 80.64,8.73 81.91,10 IN7-8.4
N$131  (via drill 0.61)
  Top 0.254: v70.48,11.27 70.48,8.09 69.21,6.82 IC17.7
  Bottom 0.254: v70.48,11.27 79.37,11.27 81.27,13.17 IN7-8.6
N$132  (via drill 0.61)
  Top 0.254: v78.1,3.64 80,5.55 80,13.17 81.91,15.08 IN7-8.8
  Bottom 0.254: v78.1,3.64 73.66,3.64 72.38,4.92 IC17.8
N$133  (via drill 0.61)
  Top 0.254: v71.75,9.36 71.75,11.9 IC17.13
  Bottom 0.254: v71.75,9.36 82.55,9.36 83.81,8.09 IN7-8.1
N$134
  Bottom 0.254: IC17.14 69.21,11.9 69.21,10 71.11,10 71.75,10.63 80,10.63 81.27,11.9 82.55,11.9 83.81,10.63 IN7-8.3
N$135
  Bottom 0.254: IC17.17 62.23,13.81 64.13,15.71 80,15.71 81.27,16.98 90.16,16.98 90.8,16.34 90.8,13.81 84.45,13.81 IN7-8.5
N$136  (via drill 0.61)
  Top 0.254: v57.78,29.68 57.78,16.98 58.41,16.34 58.41,15.08 59.05,14.44 IC17.18 | v87.62,31.58 87.62,19.52 84.45,16.34 IN7-8.7
  Bottom 0.254: v57.78,29.68 59.69,31.58 v87.62,31.58
N$137
  Bottom 0.254: IC7.2 55.88,60.8 54.61,59.52 48.89,59.52 47.62,59.52 43.81,63.34 OUT7-8.2 44.45,63.97
OC\  (via drill 0.61)
  Top 0.254: 12.06,18.25 12.06,10.63 13.33,9.36 IC1.1 | 12.06,18.25 13.33,19.52 IC2.1 | 12.06,18.25 12.06,30.95 13.33,32.22 IC3.1 13.33,34.76 12.06,36.03 12.06,42.38 13.33,43.65 13.33,44.92 IC4.1 13.33,47.46 14.6,48.73 14.6,56.35 13.33,57.62 IC5.1 13.33,60.16 13.33,62.06 12.06,63.34 12.06,69.05 13.33,70.32 IC6.1 | IC7.1 53.97,62.7 55.24,63.97 55.24,71.59 53.97,72.86 IC8.1 | v41.91,77.94 46.98,77.94 48.89,76.03 v48.89,74.13 49.53,73.5 49.53,63.34 48.89,62.7 OC\.2
  Bottom 0.254: v48.89,74.13 53.34,74.13 IC8.1 | v41.91,77.94 40.64,76.67 26.03,76.67 22.86,73.5 15.24,73.5 13.97,72.22 IC6.1
OUT00  (via drill 0.61)
  Top 0.254: v34.92,22.7 34.92,18.25 36.19,16.98 IC1.11 | v27.3,23.33 v27.3,30.31 | v66.67,38.57 67.94,39.84 67.94,51.27 66.67,52.54 IC10.15
  Bottom 0.254: v34.92,22.7 34.29,23.33 v27.3,23.33 | v27.3,30.31 28.57,31.58 34.29,31.58 34.92,32.22 34.92,37.3 45.08,37.3 47.62,39.84 62.86,39.84 64.13,38.57 v66.67,38.57
OUT01  (via drill 0.61)
  Top 0.254: v47.62,34.76 v47.62,47.46
  Bottom 0.254: v47.62,34.76 45.08,32.22 40,32.22 36.83,29.04 IC2.11 | v47.62,47.46 50.16,50 65.4,50 68.57,53.17 IC10.14
OUT02  (via drill 0.61)
  Top 0.254: v34.92,69.69 34.92,43.65 36.19,42.38 IC3.11 | v29.84,75.4 v29.84,84.92 | v75.56,86.83 75.56,58.89 71.75,55.08 IC10.13
  Bottom 0.254: v34.92,69.69 34.92,75.4 v29.84,75.4 | v29.84,84.92 33.02,88.1 74.29,88.1 v75.56,86.83
OUT03
  Bottom 0.254: IC4.11 36.83,54.45 38.1,55.71 72.38,55.71 73.66,54.45 IC10.12
OUT04
  Top 0.254: IC5.11 36.19,67.78 38.1,69.69 38.1,81.75 42.54,86.19 60.96,86.19 60.96,84.92 62.86,83.02 62.86,67.78 67.94,62.7 67.94,57.62 70.48,55.08 70.48,52.54 71.11,51.91 76.19,51.91 76.19,53.17 IC10.11
OUT05  (via drill 0.61)
  Top 0.254: v36.19,86.19 36.19,80.48 IC6.11 | v82.55,83.66 85.72,80.48 v85.72,60.16
  Bottom 0.254: v36.19,86.19 74.92,86.19 77.46,83.66 v82.55,83.66 | v85.72,60.16 80,54.45 IC10.10
OUT06  (via drill 0.61)
  Top 0.254: v79.37,66.51 79.37,57.62 81.91,55.08 IC10.9
  Bottom 0.254: v79.37,66.51 77.46,68.41 IC7.11
OUT07
  Top 0.254: IC10.7 79.37,47.46 78.1,48.73 78.1,79.21 76.83,80.48 IC8.11
PIA-A0  (via drill 0.61)
  Top 0.254: 95.88,18.25 95.88,10.63 94.61,9.36 IC11.2 93.97,7.46 v90.16,3.64 | 95.88,18.25 94.61,19.52 IC12.2 | 95.88,30.95 94.61,32.22 IC13.2 | 95.88,18.25 95.88,30.95 | 95.88,43.65 94.61,44.92 IC14.2 | 95.88,30.95 95.88,43.65 | 95.88,56.35 94.61,57.62 IC15.2 | 95.88,43.65 95.88,56.35 | 95.88,56.35 95.88,69.05 94.61,70.32 IC16.2 | IC1.3 18.41,9.36 19.04,10 19.04,13.81 19.68,14.44 19.68,16.98 18.41,18.25 18.41,19.52 IC2.3 18.41,22.06 19.68,23.33 19.68,29.68 18.41,30.95 18.41,32.22 IC3.3 18.41,34.76 19.68,36.03 19.68,42.38 18.41,43.65 18.41,44.92 IC4.3 18.41,47.46 18.41,48.09 19.68,49.37 19.68,55.08 19.04,55.71 19.04,56.98 18.41,57.62 IC5.3 18.41,60.16 18.41,63.97 19.68,65.24 19.68,67.78 19.04,68.41 19.04,69.69 18.41,70.32 IC6.3 | IC8.3 59.05,72.86 57.78,71.59 57.78,63.97 59.05,62.7 IC7.3 59.05,60.16 56.51,57.62 56.51,30.95 52.7,27.14 52.7,11.9 57.15,7.46 | 57.15,7.46 56.51,6.82 IC17.2 | 57.15,7.46 57.78,8.09 57.78,15.71 56.51,16.98 IC18.2
  Bottom 0.254: 54.61,3.64 55.88,4.92 IC17.2 | 54.61,3.64 48.89,3.64 48.26,4.28 | 48.26,4.28 46.98,5.55 CORE-IO.1 | 48.26,4.28 43.18,4.28 42.54,4.92 21.58,4.92 19.04,7.46 IC1.3 | v90.16,3.64 79.37,3.64 78.1,2.38 63.5,2.38 62.23,3.64 54.61,3.64
PIA-A1  (via drill 0.61)
  Top 0.254: IC7.4 61.59,62.7 60.32,63.97 60.32,70.32 61.59,71.59 61.59,72.86 IC8.4 | IC16.5 102.23,70.32 102.23,69.05 103.5,67.78 103.5,61.43 102.23,60.16 IC15.5 102.23,57.62 102.86,56.98 102.86,55.71 103.5,55.08 103.5,48.73 102.23,47.46 IC14.5 102.23,44.92 102.23,43.65 103.5,42.38 103.5,39.84 102.86,39.2 102.86,35.39 102.23,34.76 IC13.5 102.23,32.22 102.23,30.95 103.5,29.68 103.5,27.14 102.86,26.5 | IC11.5 102.23,9.36 103.5,10.63 103.5,16.98 102.23,18.25 102.23,19.52 IC12.5 102.23,22.06 102.86,22.7 102.86,26.5 | IC17.5 64.13,6.82 62.86,8.09 62.86,15.71 64.13,16.98 IC18.5 | 22.22,18.25 22.22,10.63 20.95,9.36 IC1.4 | 22.22,18.25 20.95,19.52 IC2.4 | 22.22,30.95 20.95,32.22 IC3.4 | 22.22,18.25 22.22,30.95 | 22.22,43.65 20.95,44.92 IC4.4 | 22.22,30.95 22.22,43.65 | 22.22,56.35 20.95,57.62 IC5.4 | 22.22,43.65 22.22,56.35 | 22.22,56.35 22.22,69.05 20.95,70.32 IC6.4 | v103.5,26.5 102.86,26.5
  Bottom 0.254: IC8.4 62.23,73.5 63.5,72.22 90.16,72.22 91.44,73.5 100.32,73.5 101.59,72.22 IC16.5 | IC1.4 21.58,7.46 23.49,5.55 43.18,5.55 CORE-IO.2 44.45,5.55 45.72,6.82 52.07,6.82 52.7,7.46 62.23,7.46 63.5,6.18 IC17.5 | v103.5,26.5 102.86,25.87 86.35,25.87 85.08,24.6 78.1,24.6 77.46,23.96 68.57,23.96 64.13,19.52 IC18.5
PIA-A2
  Top 0.254: IC7.7 69.21,62.7 67.94,63.97 67.94,71.59 69.21,72.86 IC8.7 | IC11.6 104.77,9.36 106.04,10.63 106.04,18.25 104.77,19.52 IC12.6 105.41,21.42 108.58,24.6 108.58,29.68 105.41,32.85 IC13.6 104.77,34.76 106.04,36.03 106.04,43.65 | 106.04,43.65 104.77,44.92 IC14.6 | 106.04,56.35 104.77,57.62 IC15.6 | 106.04,56.35 106.04,43.65 | 106.04,56.35 106.04,69.05 104.77,70.32 IC16.6 | IC17.6 66.67,6.82 65.4,8.09 65.4,14.44 66.67,15.71 66.67,16.98 IC18.6 | IC6.7 28.57,70.32 29.2,69.69 29.2,68.41 29.84,67.78 29.84,61.43 28.57,60.16 IC5.7 28.57,57.62 29.84,56.35 29.84,49.37 28.57,48.09 28.57,47.46 IC4.7 28.57,44.92 28.57,43.65 29.84,42.38 29.84,36.03 28.57,34.76 IC3.7 28.57,32.22 29.84,30.95 29.84,27.14 29.2,26.5 29.2,22.7 28.57,22.06 IC2.7 28.57,19.52 28.57,18.25 29.84,16.98 29.84,14.44 29.2,13.81 29.2,10 28.57,9.36 IC1.7 28.57,6.82 28.57,2.38 33.02,2.38 37.46,6.82 44.45,6.82 45.72,8.09 CORE-IO.3
  Bottom 0.254: 93.34,56.35 93.34,60.16 89.53,63.97 70.48,63.97 69.21,62.7 IC7.7 | 93.34,56.35 102.23,56.35 104.13,58.25 IC15.6 | CORE-IO.3 46.98,8.09 48.26,9.36 62.86,9.36 66.03,6.18 IC17.6 | 93.34,56.35 92.7,55.71 86.35,55.71 82.55,51.91 76.19,51.91 75.56,52.54 75.56,56.35 31.11,56.35 29.2,58.25 IC5.7
PIA-A3  (via drill 0.61)
  Top 0.254: IC11.9 112.39,9.36 113.66,10.63 113.66,16.98 112.39,18.25 112.39,19.52 IC12.9 112.39,22.06 113.02,22.7 113.02,26.5 113.66,27.14 113.66,29.68 112.39,30.95 112.39,32.22 IC13.9 112.39,34.76 113.02,35.39 113.02,39.2 113.66,39.84 113.66,43.65 | IC7.8 71.75,62.7 70.48,63.97 70.48,70.32 71.75,71.59 71.75,72.86 IC8.8 | 113.66,43.65 112.39,44.92 IC14.9 | 113.66,43.65 113.66,56.35 112.39,57.62 IC15.9 112.39,60.16 112.39,63.97 113.66,65.24 113.66,69.05 112.39,70.32 IC16.9 112.39,72.86 v112.39,74.77 | 32.38,30.95 32.38,23.33 31.11,22.06 IC2.8 31.11,19.52 32.38,18.25 32.38,14.44 31.74,13.81 31.74,8.73 IC1.8 | 32.38,30.95 31.11,32.22 IC3.8 | 32.38,30.95 32.38,43.65 31.11,44.92 IC4.8 31.11,47.46 32.38,48.73 32.38,56.35 | 32.38,56.35 31.11,57.62 IC5.8 | 32.38,56.35 32.38,69.05 31.11,70.32 IC6.8 | IC17.9 74.29,6.82 73.02,8.09 73.02,15.71 74.29,16.98 IC18.9
  Bottom 0.254: v112.39,74.77 100.32,74.77 99.05,76.03 73.66,76.03 72.38,74.77 IC8.8 | IC1.8 31.74,7.46 33.02,6.18 41.27,6.18 43.18,8.09 CORE-IO.4 44.45,8.09 45.72,9.36 46.98,9.36 47.62,10 64.77,10 65.4,9.36 70.48,9.36 72.38,7.46 | 72.38,7.46 73.66,6.18 IC17.9 | 72.38,7.46 77.46,7.46 78.1,6.82 85.08,6.82 85.72,7.46 85.72,8.73 88.89,11.9 90.8,11.9 90.8,6.82 91.44,6.18 103.5,6.18 103.5,9.36 104.13,10 110.48,10 111.75,8.73 IC11.9
PIA-A4  (via drill 0.61)
  Top 0.254: 111.12,25.87 111.12,18.25 112.39,16.98 IC11.12 | 111.12,25.87 112.39,27.14 IC12.12 | 111.12,25.87 111.12,34.76 111.75,35.39 111.75,39.2 112.39,39.84 IC13.12 112.39,42.38 112.39,43.65 111.12,44.92 111.12,56.35 | IC7.13 71.75,70.32 73.02,71.59 73.02,75.4 71.75,76.67 71.75,80.48 IC8.13 | 111.12,56.35 112.39,55.08 IC14.12 | 111.12,60.8 111.12,63.97 | 111.12,60.8 111.12,56.35 | 111.12,63.97 112.39,65.24 IC15.12 | 111.12,63.97 111.12,76.67 112.39,77.94 IC16.12 | v108.58,64.61 108.58,63.34 111.12,60.8 | IC18.12 73.66,26.5 72.38,27.77 70.48,27.77 70.48,24.6 71.75,23.33 71.75,20.79 70.48,19.52 70.48,16.98 67.94,14.44 67.94,4.28 68.57,3.64 75.56,3.64 75.56,6.82 74.29,8.09 74.29,11.9 IC17.12 | v30.47,11.9 31.11,12.54 31.11,14.44 IC1.13 31.11,16.98 29.84,18.25 29.84,25.87 31.11,27.14 IC2.13 31.11,29.68 30.47,30.31 30.47,31.58 29.84,32.22 29.84,34.76 31.11,36.03 31.11,39.84 IC3.13 31.11,42.38 29.84,43.65 29.84,48.09 31.11,49.37 31.11,52.54 IC4.13 31.11,55.08 31.11,56.35 29.84,57.62 29.84,60.16 30.47,60.8 30.47,64.61 31.11,65.24 IC5.13 31.11,67.78 29.84,69.05 29.84,74.13 31.11,75.4 31.11,77.94 IC6.13 31.11,80.48 31.11,88.1 75.56,88.1 78.73,84.92 78.73,71.59 v80.64,69.69
  Bottom 0.254: 80.64,64.61 v108.58,64.61 | 80.64,64.61 76.19,64.61 72.38,68.41 IC7.13 | IC17.12 73.66,13.81 72.38,15.08 66.03,15.08 65.4,14.44 65.4,10.63 46.98,10.63 CORE-IO.5 45.72,10.63 44.45,11.9 v30.47,11.9 | v80.64,69.69 80.64,64.61
PIA-A5  (via drill 0.61)
  Top 0.254: IC11.15 104.77,16.98 103.5,18.25 103.5,25.23 104.77,26.5 104.77,27.14 IC12.15 104.77,29.68 103.5,30.95 103.5,38.57 104.77,39.84 IC13.15 104.77,42.38 103.5,43.65 103.5,47.46 104.77,48.73 104.77,52.54 IC14.15 104.77,55.08 103.5,56.35 103.5,60.16 104.77,61.43 104.77,65.24 IC15.15 104.77,67.78 103.5,69.05 103.5,76.67 104.77,77.94 IC16.15 | IC7.14 69.21,70.32 70.48,71.59 70.48,79.21 69.21,80.48 IC8.14 | 27.3,51.27 27.3,43.65 28.57,42.38 IC3.14 28.57,39.84 27.3,38.57 27.3,31.58 28.57,30.31 28.57,29.68 IC2.14 28.57,27.14 28.57,23.33 27.3,22.06 27.3,18.25 | 27.3,51.27 28.57,52.54 IC4.14 | 27.3,63.97 28.57,65.24 IC5.14 | 27.3,51.27 27.3,63.97 | 27.3,63.97 27.3,76.67 28.57,77.94 IC6.14 | IC17.15 66.67,14.44 67.94,15.71 67.94,23.33 66.67,24.6 IC18.15 | 27.3,18.25 28.57,16.98 IC1.14 | 27.3,18.25 27.3,1.74 44.45,1.74 47.62,4.92 47.62,9.36 45.72,9.36 44.45,10.63 CORE-IO.6 | v47.62,75.4 40.64,75.4 v40.64,77.94
  Bottom 0.254: IC16.15 104.13,79.84 102.86,81.11 91.44,81.11 90.8,80.48 80.64,80.48 80,79.84 71.11,79.84 69.84,81.11 IC8.14 68.57,81.11 64.77,77.3 53.97,77.3 52.07,75.4 v47.62,75.4 | IC18.15 66.03,25.23 64.77,23.96 47.62,23.96 46.98,24.6 37.46,24.6 34.92,27.14 34.92,30.31 30.47,30.31 29.2,29.04 IC2.14 | v40.64,77.94 40,77.3 30.47,77.3 29.2,78.58 IC6.14
PIA-A6  (via drill 0.61)
  Top 0.254: v60.32,71.59 60.32,79.21 61.59,80.48 IC8.17 60.96,82.39 59.69,83.66 48.26,83.66 v48.26,82.39 | IC11.16 102.23,16.98 101.59,17.61 101.59,18.88 100.96,19.52 100.96,22.06 102.23,23.33 102.23,27.14 IC12.16 102.23,29.68 100.96,30.95 100.96,34.76 102.23,36.03 102.23,39.84 IC13.16 102.23,42.38 100.96,43.65 100.96,51.27 | 100.96,51.27 102.23,52.54 IC14.16 | 100.96,63.97 102.23,65.24 IC15.16 | 100.96,63.97 100.96,51.27 | 100.96,69.69 100.96,63.97 | 100.96,69.69 100.96,72.86 101.59,73.5 101.59,77.3 102.23,77.94 IC16.16 | v98.42,69.69 100.96,69.69 | IC17.16 64.13,14.44 65.4,15.71 65.4,23.33 64.13,24.6 IC18.16 | IC1.17 20.95,16.98 19.68,18.25 19.68,22.06 20.95,23.33 20.95,27.14 IC2.17 20.95,29.68 19.68,30.95 19.68,34.76 20.95,36.03 20.95,39.84 IC3.17 20.95,42.38 19.68,43.65 19.68,48.09 20.95,49.37 20.95,52.54 IC4.17 20.95,55.08 19.68,56.35 19.68,63.97 20.95,65.24 IC5.17 20.95,67.78 19.68,69.05 19.68,76.67 20.95,77.94 IC6.17 20.95,80.48 v20.95,84.29 | v40,14.44 44.45,14.44 45.72,13.17 CORE-IO.7
  Bottom 0.254: v60.32,71.59 61.59,70.32 IC7.17 62.23,69.69 63.5,70.95 90.16,70.95 91.44,69.69 v98.42,69.69 | CORE-IO.7 46.98,13.17 48.89,11.27 62.23,11.27 63.5,12.54 IC17.16 | v40,14.44 36.83,17.61 22.86,17.61 21.58,16.34 IC1.17 | v48.26,82.39 47.62,83.02 45.72,83.02 45.08,82.39 42.54,84.92 31.11,84.92 29.84,83.66 21.58,83.66 v20.95,84.29
PIA-A7  (via drill 0.61)
  Top 0.254: 17.14,25.87 17.14,18.25 18.41,16.98 IC1.18 18.41,14.44 17.77,13.81 v17.77,11.9 | 17.14,25.87 18.41,27.14 IC2.18 | 17.14,38.57 18.41,39.84 IC3.18 | 17.14,25.87 17.14,38.57 | 17.14,51.27 18.41,52.54 IC4.18 | 17.14,38.57 17.14,51.27 | 17.14,51.27 17.14,63.97 18.41,65.24 IC5.18 18.41,67.78 18.41,68.41 17.14,69.69 17.14,76.67 18.41,77.94 IC6.18 | 93.34,25.87 93.34,18.25 94.61,16.98 IC11.19 | 93.34,25.87 94.61,27.14 IC12.19 | 93.34,38.57 94.61,39.84 IC13.19 | 93.34,38.57 93.34,25.87 | 93.34,51.27 94.61,52.54 IC14.19 | 93.34,51.27 93.34,38.57 | 93.34,51.27 93.34,63.97 94.61,65.24 IC15.19 94.61,67.78 93.34,69.05 93.34,72.86 94.61,74.13 94.61,77.94 IC16.19 | IC17.19 56.51,14.44 55.24,15.71 55.24,23.33 56.51,24.6 IC18.19 56.51,27.14 56.51,29.68 59.05,32.22 59.05,58.89 60.32,60.16 60.32,62.7 59.05,63.97 59.05,67.78 IC7.18 | v57.78,76.03 57.78,79.21 59.05,80.48 IC8.18
  Bottom 0.254: IC17.19 55.88,13.81 54.61,15.08 53.34,15.08 52.7,14.44 45.72,14.44 44.45,13.17 CORE-IO.8 43.18,13.17 30.47,13.17 29.84,12.54 18.41,12.54 v17.77,11.9 | 60.32,76.03 60.32,76.67 92.07,76.67 93.97,78.58 IC16.19 | 60.32,76.03 60.32,72.86 59.69,72.22 59.05,72.22 59.05,70.32 IC7.18 | 60.32,76.03 v57.78,76.03
PIA-B0  (via drill 0.61)
  Top 0.254: IC9.1 64.13,34.76 62.86,36.03 62.86,43.65 64.13,44.92 IC10.1 | v48.26,25.87 48.26,23.33 46.35,21.42 CORE-IO.13
  Bottom 0.254: v48.26,25.87 54.61,32.22 64.13,32.22 IC9.1
PIA-B1  (via drill 0.61)
  Top 0.254: IC9.2 66.67,34.76 65.4,36.03 65.4,43.65 66.67,44.92 IC10.2 | v38.1,44.92 38.1,27.14 43.81,21.42 CORE-IO.14
  Bottom 0.254: v38.1,44.92 62.86,44.92 63.5,44.28 64.77,44.28 66.03,45.55 IC10.2
PIA-B2  (via drill 0.61)
  Top 0.254: IC10.3 69.21,44.92 70.48,43.65 70.48,36.03 69.21,34.76 IC9.3 68.57,32.85 68.57,31.58 63.5,31.58 v60.32,34.76 | v47.62,32.22 47.62,27.14 45.72,27.14 45.08,26.5 45.08,25.23 46.35,23.96 CORE-IO.15
  Bottom 0.254: v47.62,32.22 50.16,34.76 v60.32,34.76
PIA-B3
  Top 0.254: IC19.1 43.18,50.63 41.91,49.37 41.91,25.87 43.81,23.96 CORE-IO.16
PIA-B4  (via drill 0.61)
  Top 0.254: v48.89,34.76 48.89,48.73 45.08,48.73 IC19.2
  Bottom 0.254: v48.89,34.76 45.08,30.95 40.64,30.95 39.37,29.68 39.37,27.14 44.45,27.14 45.72,25.87 CORE-IO.17
PIA-B5
  Top 0.254: IC19.3 44.45,45.55 46.35,43.65 46.35,30.31 45.08,29.04 45.08,27.77 43.81,26.5 CORE-IO.18
PIA-B6  (via drill 0.61)
  Top 0.254: IC9.4 72.38,32.85 73.66,31.58 75.56,31.58 75.56,43.65 76.83,44.92 IC10.6 | v40.64,29.68 39.37,30.95 v39.37,42.38
  Bottom 0.254: v40.64,29.68 44.45,29.68 45.72,28.41 CORE-IO.19 | v39.37,42.38 62.86,42.38 63.5,43.02 73.66,43.02 76.19,45.55 IC10.6
PIA-B7
  Top 0.254: IC19.5 44.45,40.48 45.72,39.2 45.72,30.95 43.81,29.04 CORE-IO.20
  Bottom 0.254: DEVSEL.2 54.61,33.49 48.26,27.14 45.72,27.14 44.45,28.41 CORE-IO.20
VCC  (via drill 0.61)
  Top 0.508: CORE-IO.9 45.72,15.71 43.81,17.61 CORE-IO.12 | v51.43,15.71 51.43,13.81 BYP18.1 | v53.97,20.79 53.97,24.6 IC18.20 | BYP6.1 11.43,79.21 12.7,79.21 IC6.20 13.33,77.94 13.33,74.77 11.43,72.86 11.43,67.78 10.79,67.14 BYP5.1 10.79,65.88 11.43,65.24 11.43,62.7 12.06,62.06 12.06,53.81 | IC1.20 13.33,16.98 14.6,18.25 14.6,25.87 13.33,27.14 IC2.20 13.33,29.68 14.6,30.95 14.6,38.57 13.33,39.84 IC3.20 | 12.06,53.81 12.7,53.81 IC4.20 13.33,52.54 12.06,51.27 12.06,43.65 10.79,42.38 10.79,41.74 BYP3.1 | 12.06,53.81 11.43,53.81 BYP4.1 | v36.19,23.96 34.92,25.23 v34.92,38.57 34.92,42.38 32.38,44.92 32.38,47.46 v33.65,48.73 | BYP7.1 52.07,69.05 53.34,69.05 IC7.20 | 52.7,81.75 53.34,81.75 IC8.20 | 52.7,81.75 52.07,81.75 BYP8.1 | 52.7,81.75 52.7,71.59 53.97,70.32 IC7.20 | BYP17.1 50.16,53.17 50.16,52.54 50.8,51.91 IC19.16 52.7,51.27 52.7,66.51 53.97,67.78 IC7.20 | BYP10.1 62.23,53.81 63.5,53.81 IC10.16 | BYP9.1 61.59,41.74 62.23,42.38 62.23,46.82 64.13,48.73 64.13,52.54 IC10.16 | BYP16.1 90.16,79.21 91.44,79.21 IC16.20 92.07,77.94 90.8,76.67 90.8,66.51 | 90.8,66.51 91.44,66.51 IC15.20 92.07,65.24 92.07,62.06 90.16,60.16 90.16,55.08 89.53,54.45 BYP14.1 | 90.8,66.51 90.16,66.51 BYP15.1 | IC18.11 76.83,27.14 76.83,32.22 IC9.6 76.83,34.76 78.1,36.03 78.1,42.38 | 83.18,60.8 81.91,59.52 BYP20.1 | 83.18,60.8 84.45,62.06 v84.45,79.21 84.45,80.48 83.18,81.75 JP2.2 | 78.1,42.38 80.64,44.92 80.64,50 83.18,52.54 83.18,60.8 | 78.1,42.38 78.1,47.46 77.46,48.09 72.38,48.09 67.94,52.54 67.94,55.71 66.03,55.71 64.77,54.45 IC10.16 | BYP13.1 90.16,41.11 91.44,41.11 IC13.20 92.07,39.84 90.8,38.57 90.8,28.41
  Top 0.508: 90.8,28.41 91.44,28.41 IC12.20 92.07,27.14 90.8,25.87 90.8,15.71 | 90.8,28.41 90.16,28.41 BYP12.1 | 90.8,15.71 90.16,15.71 BYP11.1 | 90.8,15.71 91.44,15.71 IC11.20 | IC11.11 114.93,16.98 113.66,18.25 113.66,25.87 114.93,27.14 IC12.11 114.93,29.68 113.66,30.95 113.66,38.57 114.93,39.84 IC13.11 114.93,42.38 116.2,43.65 116.2,51.27 114.93,52.54 IC14.11 114.93,55.08 114.93,56.35 113.66,57.62 113.66,63.97 114.93,65.24 IC15.11 114.93,67.78 114.93,69.05 113.66,70.32 113.66,76.67 114.93,77.94 IC16.11
  Bottom 0.508: BYP19.1 52.07,25.87 53.34,25.87 IC18.20 | BYP18.1 52.07,13.17 53.34,13.17 IC17.20 | 48.89,15.71 46.98,15.71 CORE-IO.9 | 48.89,15.71 v51.43,15.71 | 48.89,15.71 v53.97,20.79 | BYP5.1 11.43,66.51 12.7,66.51 IC5.20 | BYP1.1 11.43,15.71 12.7,15.71 IC1.20 | BYP2.1 11.43,28.41 12.7,28.41 IC2.20 | BYP3.1 11.43,41.11 12.7,41.11 IC3.20 13.33,42.38 4.44,42.38 4.44,40.48 5.08,39.84 6.34,39.84 7.62,38.57 v34.92,38.57 42.54,38.57 IC19.6 | v36.19,23.96 37.46,23.96 43.18,18.25 CORE-IO.12 | BYP9.1 62.23,41.11 63.5,41.11 IC9.16 | IC10.16 64.13,52.54 53.97,52.54 52.7,51.27 IC19.16 50.16,51.27 48.89,50 34.92,50 v33.65,48.73 | BYP14.1 90.16,53.81 91.44,53.81 IC14.20 | v84.45,79.21 88.89,79.21 BYP16.1 | IC17.11 77.46,13.81 78.1,14.44 87.62,14.44 88.89,15.71 BYP11.1 | IC11.20 92.7,15.08 93.97,13.81 113.02,13.81 114.3,15.08 IC11.11 | JP2.2 83.18,81.75 107.31,81.75 108.58,80.48 108.58,77.94 109.21,77.3 113.02,77.3 114.3,78.58 IC16.11

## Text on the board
Top: PA8PDP/VRS | Component Side
Bottom: Solder Side
tValues: RealConsole I/O - Rev.2 | + | - | - | +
